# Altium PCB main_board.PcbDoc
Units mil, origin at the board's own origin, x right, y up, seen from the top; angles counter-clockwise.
Board outline 7810 x 5890 mil, 2 copper layers (Top Layer, Bottom Layer); 105 components, 115 nets, 422 pads, 69 vias.
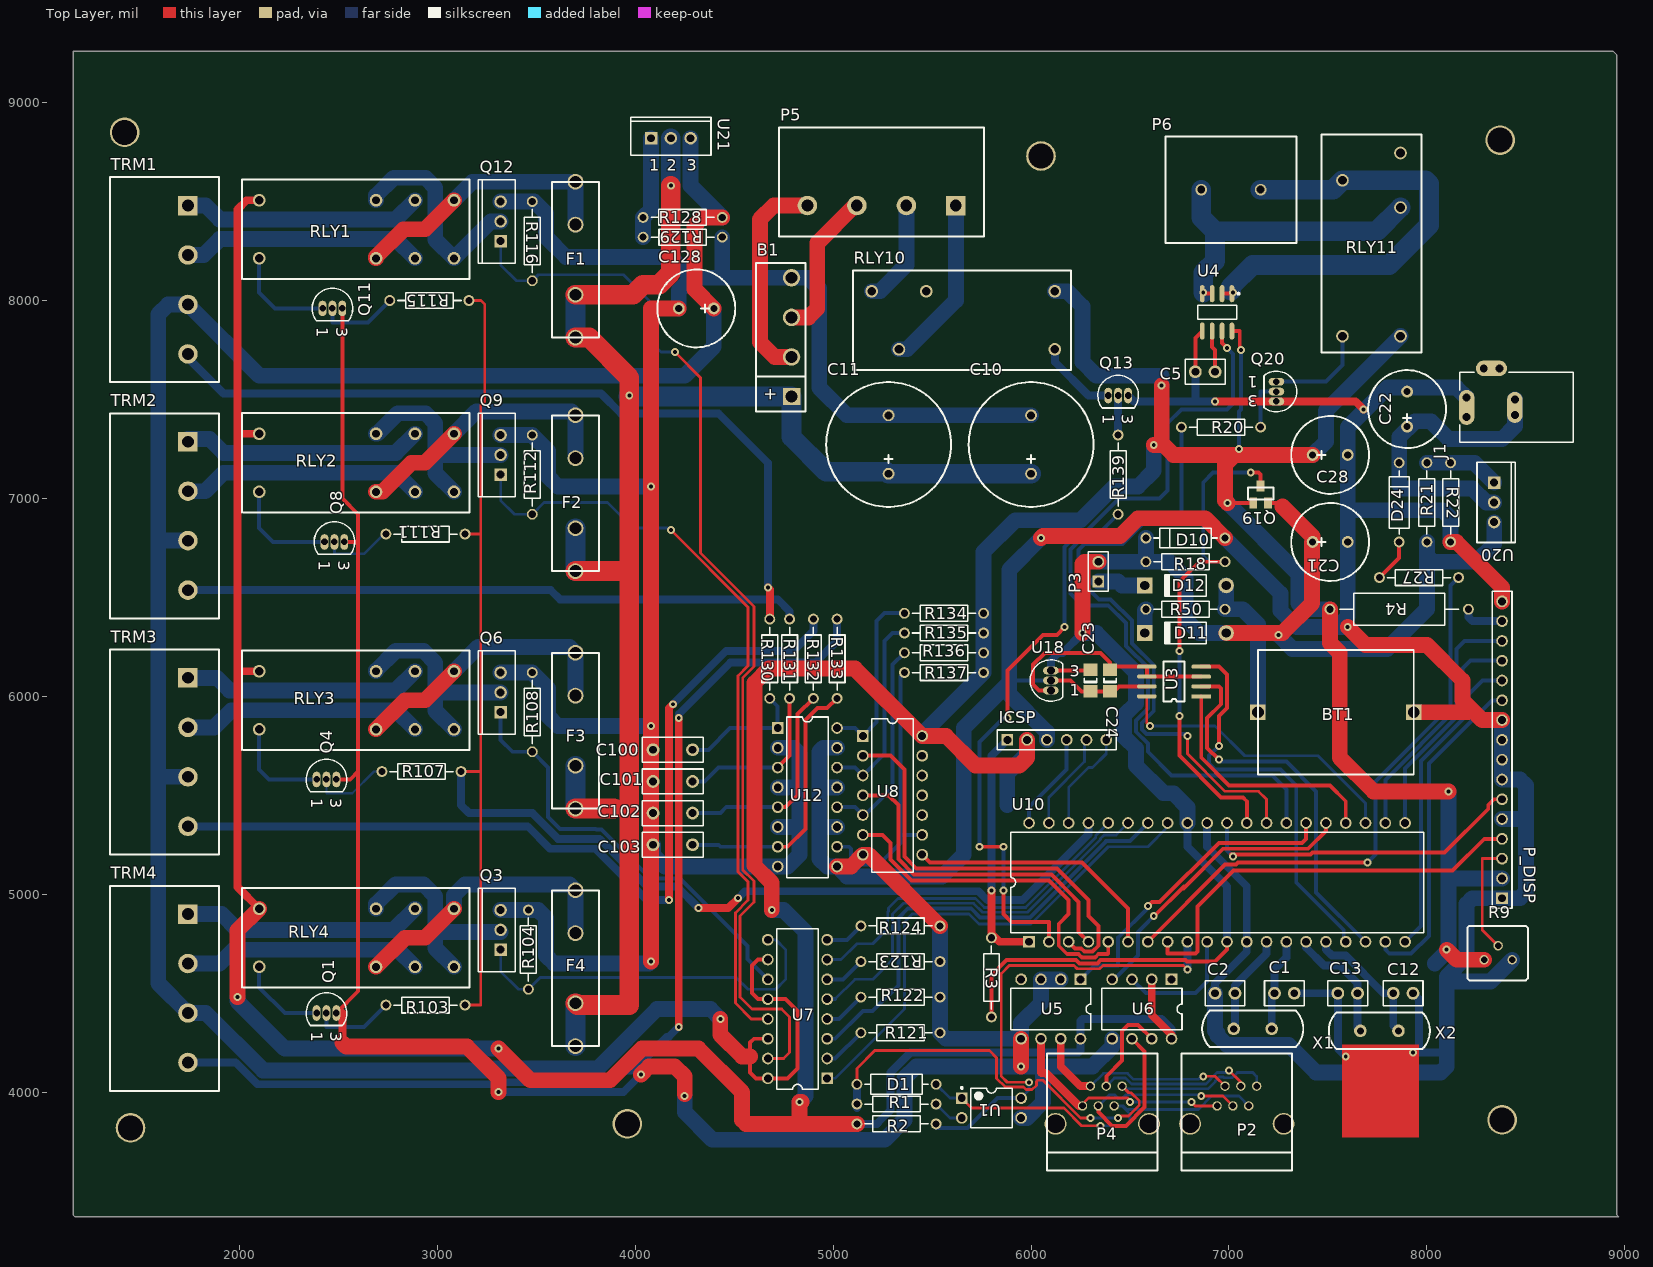
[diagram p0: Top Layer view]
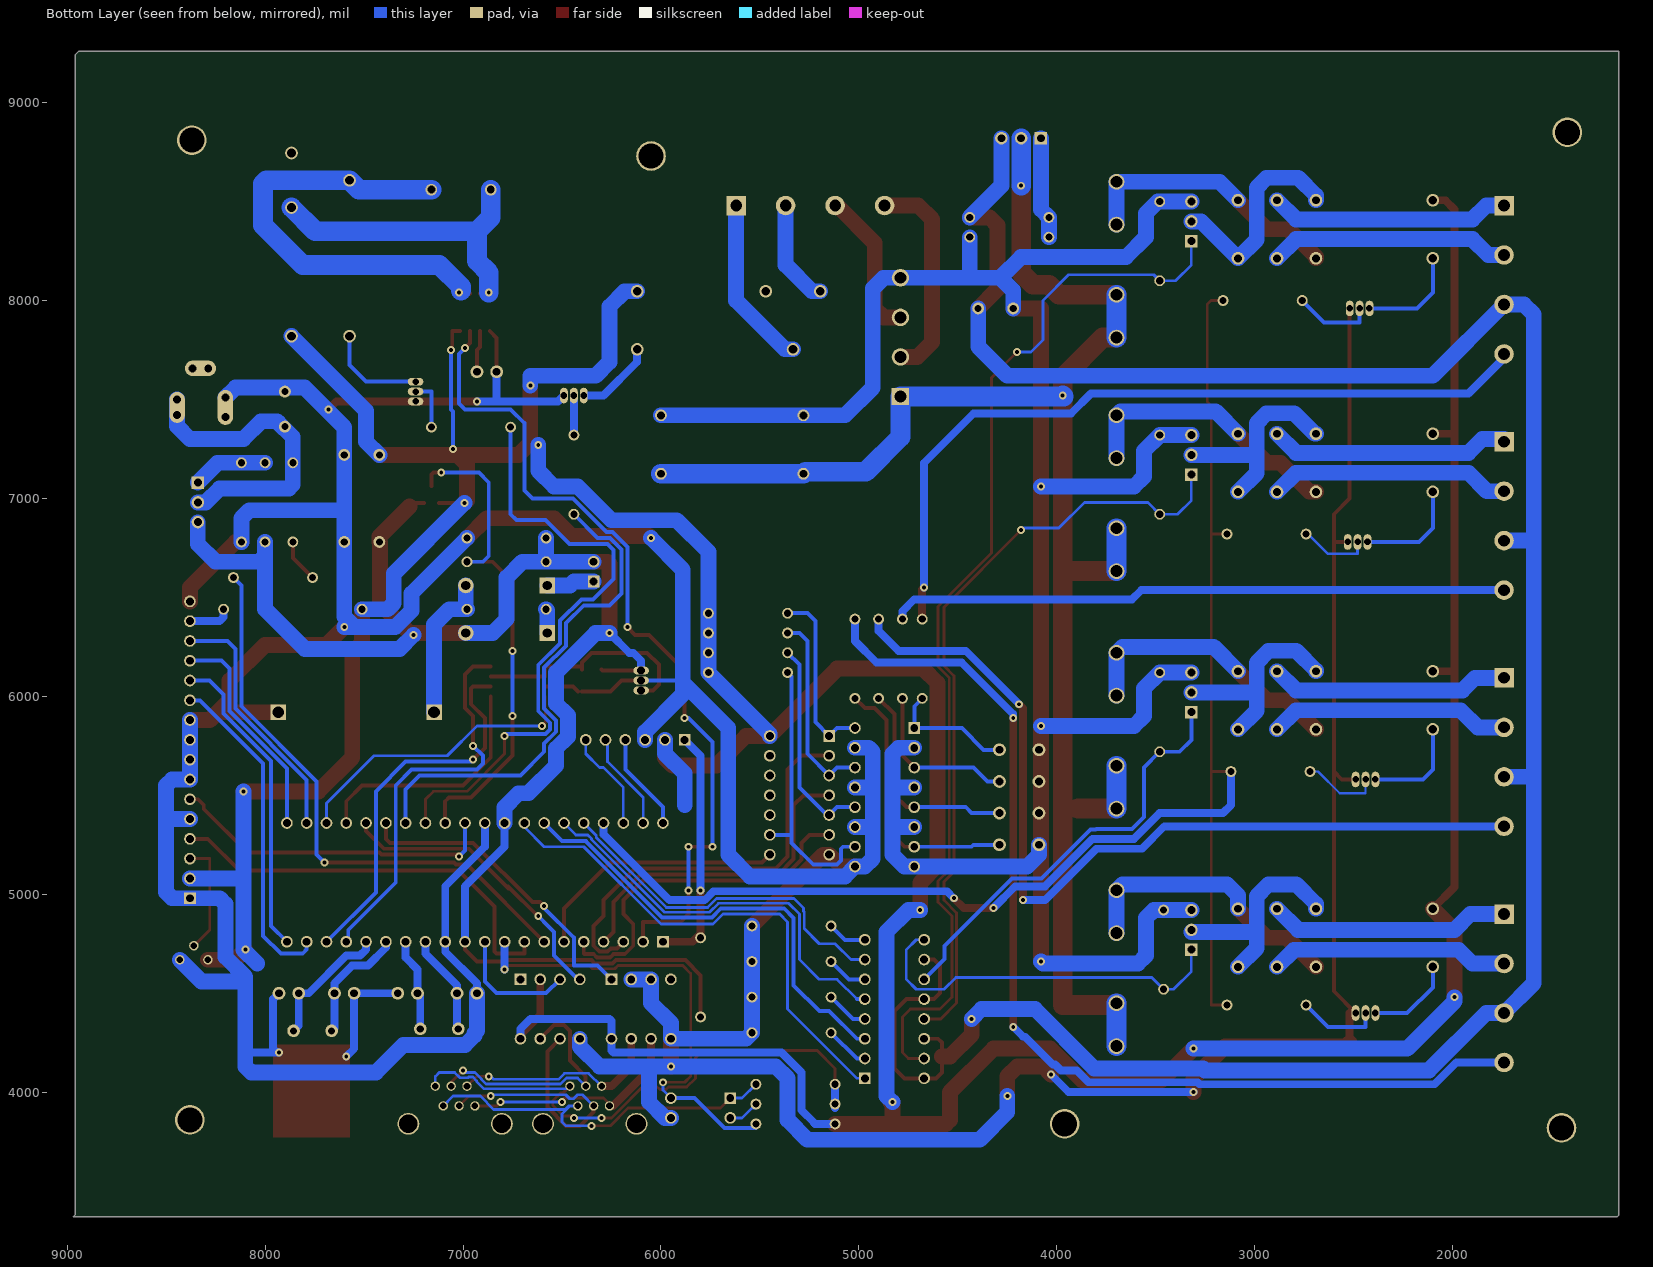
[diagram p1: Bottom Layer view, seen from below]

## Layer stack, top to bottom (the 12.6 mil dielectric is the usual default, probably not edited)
Top Layer: signal copper 1.4
Dielectric: dielectric 12.6, FR-4, Dk 4.8
Bottom Layer: signal copper 1.4

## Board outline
1160,3490 1160,9260 8940,9260 8960,9240 8960,3380 8970,3370 1170,3370 1160,3380

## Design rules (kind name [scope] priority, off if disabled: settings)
Clearance [All] p1: gap=10
ComponentClearance [All] p1: gap=10 collisioncheckmode=3 verticalgap=10
PolygonConnect [All] p1: connectstyle=Relief reliefconductorwidth=10 reliefentries=4 polygonreliefangle="90 Angle"
RoutingCorners [All] p1: cornerstyle=45-Degree minsetback=20 maxsetback=20
RoutingPriority [InNet('GND')] p1: routingpriority=0
RoutingVias [All] p1: holewidth=20 width=40 viastyle="Through Hole" minholewidth=20 minwidth=40 maxholewidth=20 maxwidth=40
SolderMaskExpansion [All] p1: expansion=4
TestPointUsage [All] p1: valid=0 allowmultiple=FALSE
Testpoint [(IsPad And (OnTopLayer Or OnBottomLayer))] p1: side=3 testpointundercomponent=TRUE minsize=40 maxsize=100 preferedsize=60 minholesize=0 maxholesize=40 preferedholesize=32 testpointgrid=1 style=297 order=0-112345678
Width [All] p1: maxlimit=100 minlimit=10 preferedwidth=14
16 further rules are at their usual default settings.

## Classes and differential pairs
component class "Sensor frontend": C100 C101 C102 C103 D1 R1 R2 R130 R131 R132 R133 R134 R135 R136 R137 U1 U8 U12
component class main: BT1 C1 C2 C5 C12 C13 C21 C22 C23 C24 C28 D10 D11 D12 D24 ICSP J1 P2 P3 P4 P6 P_DISP Q19 Q20 R3 R4 R9 R18 R20 R21 R22 R27 R50 RLY9 RLY11 U3 U4 U5 U6 U10 U18 U20 U? X1 X2
component class MTR_DRV1: B1 C10 C11 C128 F1 F2 F3 F4 P5 Q1 Q3 Q4 Q6 Q8 Q9 Q11 Q12 Q13 R103 R104 R107 R108 R111 R112 R115 R116 R121 R122 R123 R124 R128 R129 R139 RLY1 RLY2 RLY3 RLY4 RLY10 TRM1 TRM2 TRM3 TRM4 U7 U21 »»»

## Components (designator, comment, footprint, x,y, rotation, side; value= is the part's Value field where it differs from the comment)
B1 "BRIDGE" BRIDGE 4860,7440 r90 top
BT1 "Battery" batt 7540,5920 r180 top
C1 "Cap" VP32-3.2 7280,4500 r180 top
C2 "Cap" VP32-3.2 6980,4500 r0 top
C5 "Cap" VP32-3.2 6880,7640 r0 top
C10 "Cap Pol1" Capacitor2200u50v 6000,7420 r270 top
C11 "Cap Pol1" Capacitor2200u50v 5280,7420 r270 top
C12 "Cap" VP32-3.2 7880,4500 r180 top
C13 "Cap" VP32-3.2 7600,4500 r0 top
C21 "Cap" Capacitor470u25v 7600,6780 r180 top
C22 "Cap" Capacitor470u25v 7900,7540 r270 top
C23 "Cap Semi" C1206 6300,6080 r90 top
C24 "Cap Semi" C1206 6400,6080 r90 top
C28 "Cap" Capacitor470u25v 7600,7220 r180 top
C100 "Cap" VP45-3.2 4190,5730 r0 top
C101 "Cap" VP45-3.2 4190,5570 r0 top
C102 "Cap" VP45-3.2 4190,5410 r0 top
C103 "Cap" VP45-3.2 4190,5250 r0 top
C128 "Cap" Capacitor470u25v 4220,7960 r0 top
D1 "13V" DIODE-0.4 5320,4040 r0 top
D10 "6V" DIODE-0.4 6780,6800 r180 top
D11 "Diode 1N4001" DO-41 6780,6320 r180 top
D12 "5817" DO-41 6780,6560 r180 top
D24 "9V" DIODE-0.4 7860,6980 r90 top
F1 "Fuse5mm" Fuse5mm 3580,8600 r270 top
F2 "Fuse5mm" Fuse5mm 3580,7420 r270 top
F3 "Fuse5mm" Fuse5mm 3580,6220 r270 top
F4 "Fuse5mm" Fuse5mm 3580,5020 r270 top
ICSP "Header 6" HDR1X6 5880,5780 r0 top
J1 "PWR2.5" KLD-0202 8740,7460 r180 top
P2 "Header 6" PHONE_6 7040,3840 r0 top
P3 "Header 2" HDR1X2 6340,6580 r90 top
P4 "Header 6" PHONE_6 6360,3840 r0 top
P5 "4XTERMINAL" BLK_TERMX4 5620,8480 r180 top
P6 "Header 2" BLOCK_X2_762mm 6860,8560 r0 top
P_DISP "Header 16" HDR1X16 8380,4980 r90 top
Q1 "P2N2222A" 29-04 2440,4400 r270 top
Q3 "IRF3205" TO-220AB 3320,4820 r90 top
Q4 "P2N2222A" 29-04 2440,5580 r270 top
Q6 "IRF3205" TO-220AB 3320,6020 r90 top
Q8 "P2N2222A" 29-04 2480,6780 r270 top
Q9 "IRF3205" TO-220AB 3320,7220 r90 top
Q11 "P2N2222A" 29-04 2470,7960 r270 top
Q12 "IRF3205" TO-220AB 3320,8400 r90 top
Q13 "P2N2222A" 29-04 6440,7520 r270 top
Q19 "IRHM9150" "SSOT-3 - duplicate" 7160,7020 r0 top
Q20 "P2N2222A" 29-04 7240,7540 r180 top
R1 "Res1" AXIAL-0.4 5320,3940 r180 top
R2 "Res1" AXIAL-0.4 5320,3840 r0 top
R3 "Res1" AXIAL-0.4 5800,4580 r270 top
R4 "Res1" AXIAL-0.7 7860,6440 r180 top
R9 "Res Tap" RPOT 8360,4740 r180 top
R18 "Res1" AXIAL-0.4 6780,6680 r0 top
R20 "Res1" AXIAL-0.4 6960,7360 r180 top
R21 "Res1" AXIAL-0.4 8000,6980 r90 top
R22 "Res1" AXIAL-0.4 8120,6980 r270 top
R27 "Res1" AXIAL-0.4 7960,6600 r0 top
R50 "Res1" AXIAL-0.4 6780,6440 r180 top
R103 "Res1" AXIAL-0.4 2940,4440 r0 top
R104 "Res1" AXIAL-0.4 3460,4720 r270 top
R107 "Res1" AXIAL-0.4 2920,5620 r0 top
R108 "Res1" AXIAL-0.4 3480,5920 r270 top
R111 "Res1" AXIAL-0.4 2940,6820 r0 top
R112 "Res1" AXIAL-0.4 3480,7120 r270 top
R115 "Res1" AXIAL-0.4 2960,8000 r0 top
R116 "Res1" AXIAL-0.4 3480,8300 r270 top
R121 "Res1" AXIAL-0.4 5340,4300 r180 top
R122 "Res1" AXIAL-0.4 5340,4480 r180 top
R123 "Res1" AXIAL-0.4 5340,4660 r180 top
R124 "Res1" AXIAL-0.4 5340,4840 r180 top
R128 "Res1" AXIAL-0.4 4240,8420 r180 top
R129 "Res1" AXIAL-0.4 4240,8320 r0 top
R130 "Res1" AXIAL-0.4 4680,6190 r90 top
R131 "Res1" AXIAL-0.4 4780,6190 r90 top
R132 "Res1" AXIAL-0.4 4900,6190 r90 top
R133 "Res1" AXIAL-0.4 5020,6190 r90 top
R134 "Res1" AXIAL-0.4 5560,6420 r180 top
R135 "Res1" AXIAL-0.4 5560,6320 r180 top
R136 "Res1" AXIAL-0.4 5560,6220 r180 top
R137 "Res1" AXIAL-0.4 5560,6120 r180 top
R139 "Res1" AXIAL-0.4 6440,7120 r90 top
RLY1 "RELAY2" DPDT_Relay 2100,8360 r180 top
RLY2 "RELAY2" DPDT_Relay 2100,7180 r180 top
RLY3 "RELAY2" DPDT_Relay 2100,5980 r180 top
RLY4 "RELAY2" DPDT_Relay 2100,4780 r180 top
RLY10 "RELAY1" SPDT 6120,7900 r0 top
RLY11 "RELAY1" SPDT 7720,7820 r270 top
TRM1 "4XTERMINAL" BLK_TERMX4 1740,8480 r270 top
TRM2 "4XTERMINAL" BLK_TERMX4 1740,7286.67 r270 top
TRM3 "4XTERMINAL" BLK_TERMX4 1740,6093.33 r270 top
TRM4 "4XTERMINAL" BLK_TERMX4 1740,4900 r270 top
U1 "Optoisolator1" DIP-4 5800,3920 r0 top
U3 "AT45DB161" SOP8 6860,6000 r180 top
U4 "ACS712" 751-05_N 6940,7940 r270 top
U5 "RS485 (RX)" PA8 6100,4420 r180 top
U6 "RS485 (TX)" PA8 6560,4420 r180 top
U7 "ILD74" DIP-16 4820,4420 r90 top
U8 "MC74HC14AN" 646-06 5300,5500 r270 top
U10 "PIC18F458-E/P" PDIP600-40 6940,5060 r0 top
U12 "ILD74" DIP-16 4870,5490 r270 top
U18 "L78L05ABZ" TO92 6100,6080 r0 top
U20 "LM317T" 221A-06 8340,6980 r270 top
U21 "LM317T" 221A-06 4180,8820 r0 top
X1 "XTAL" XTAL 7120,4320 r0 top
X2 "XTAL" XTAL 7760,4310 r180 top

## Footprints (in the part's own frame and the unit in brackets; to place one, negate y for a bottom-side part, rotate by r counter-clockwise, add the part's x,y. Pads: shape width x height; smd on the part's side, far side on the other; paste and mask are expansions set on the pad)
29-04 [mm] "TO, Flat Index; 3 In-Line, Axial Leads; Body Dia. 4.8mm; Leads 0.48 x 0.5 mm (max)"
  oval 2x1 hole 0.838: 1(0,-1.27) 2(0,0) 3(0,1.27)
  silkscreen extent -2.6,-2.6 1.6,2.6
221A-06 [mm] "TO, Thru-Hole, Vertical, Heatsink Mounted; 3 In-Line Leads; Pitch 2.54 mm"
  rect 1.6x1.6 hole 1.016: 1(-2.54,0)
  round 1.6 hole 1.016: 2(0,0) 3(2.54,0)
  silkscreen extent -5.15,-2.2 5.15,2.7
646-06 [mm] "DIP; 14 Leads; Row Spacing 7.62 mm; Pitch 2.54 mm"
  rect 1.5x1.5 hole 1.016: 1(-7.62,-3.81)
  round 1.5 hole 1.016: 2(-5.08,-3.81) 3(-2.54,-3.81) 4(0,-3.81) 5(2.54,-3.81) 6(5.08,-3.81) 7(7.62,-3.81) 8(7.62,3.81) 9(5.08,3.81) 10(2.54,3.81) 11(0,3.81) 12(-2.54,3.81) 13(-5.08,3.81) 14(-7.62,3.81)
  silkscreen extent -9.85,-2.65 9.85,2.65
751-05_N [mm] "SOIC, 8-Leads, Body 4.9x3.9mm, Pitch 1.27mm, IPC Medium Density"
  oval 2.2x0.6 smd: 1(-2.4,1.905) 2(-2.4,0.635) 3(-2.4,-0.635) 4(-2.4,-1.905) 5(2.4,-1.905) 6(2.4,-0.635) 7(2.4,0.635) 8(2.4,1.905)
  silkscreen extent -2.52,-2.5 0.9,2.88, body extent -2,-2.5 2,2.5, height 1.75
AXIAL-0.4 [mm] "Axial Device, Thru-Hole; 2 Leads; 0.4 in Pin Spacing"
  round 1.4 hole 0.914: 1(-5.08,0) 2(5.08,0)
  silkscreen extent -4.06,-1.02 4.06,1.02
AXIAL-0.7 [mm] "Variable Resistor; 2 Leads"
  round 1.4 hole 0.914: 1(-8.89,0) 2(8.89,0)
  silkscreen extent -7.62,-2.03 7.62,2.03
batt [mm]
  rect 2x2 hole 1.5: 1(10,0) 2(-10,0)
  silkscreen extent -10,-8 10,8
BLK_TERMX4 [mm] "4 PIN BLOCK TERMINCAL (6.35MM PITCH)"
  rect 2.5x2.5 hole 1.5: 0(0,0)
  round 2.5 hole 1.5: 1(6.35,0) 2(12.7,0) 3(19.05,0)
  silkscreen extent -3.63,-10 22.68,4
BLOCK_X2_762mm [mm]
  round 1.5 hole 1.016: 1(0,0) 2(7.62,0)
  silkscreen extent -4.6,-6.85 12.22,6.85
BRIDGE [mil] "KBL401"
  rect 88x88 hole 60: 1(75,70)
  round 88 hole 60: 2(275,70) 3(475,70) 4(675,70)
  silkscreen extent 0,0 750,250
C1206 [mm] "Chip Capacitor; Body 3.2 x 1.6 mm (LxW typ)"
  rect 1.6x1.8 smd: 1(-1.4,0) 2(1.4,0)
  silkscreen extent -0.3,-0.8 0.3,0.8
Capacitor470u25v [mil]
  round 60 hole 36: 1(177.17,0) 2(0,0)
  silkscreen extent -108,-197 285,197
Capacitor2200u50v [mil]
  round 60 hole 40: 1(295.28,0) 2(0,0)
  silkscreen extent -167,-315 462,315
DIODE-0.4 [mm] "Diode, Thru-Hole; 2 Leads; 0.4 in Pin Spacing"
  round 1.4 hole 0.914: 1(-5.08,0) 2(5.08,0)
  silkscreen extent -4.06,-1.27 4.06,1.27
DIP-4 [mm] "DIP; 4 Leads; Row Spacing 7.62 mm; Pitch 2.54 mm"
  rect 1.5x1.5 hole 1.016: 1(-3.81,1.27)
  round 1.5 hole 1.016: 2(-3.81,-1.27) 3(3.81,-1.27) 4(3.81,1.27)
  silkscreen extent -3.93,-2.55 2.65,2.69, body extent -3.15,-2.5 3.15,2.5, height 5.6
DIP-16 [mm] "DIP; 16 Leads; Row Spacing 7.62 mm; Pitch 2.54 mm"
  rect 1.5x1.5 hole 1.016: 1(-8.89,-3.81)
  round 1.5 hole 1.016: 2(-6.35,-3.81) 3(-3.81,-3.81) 4(-1.27,-3.81) 5(1.27,-3.81) 6(3.81,-3.81) 7(6.35,-3.81) 8(8.89,-3.81) 9(8.89,3.81) 10(6.35,3.81) 11(3.81,3.81) 12(1.27,3.81) 13(-1.27,3.81) 14(-3.81,3.81) 15(-6.35,3.81) 16(-8.89,3.81)
  silkscreen extent -10.3,-2.65 10.3,2.65
DO-41 [mm] "Diode, Axial; Body 5.2 x 2.7 mm (LxDia. max), Lead Dia. 0.86 mm (max)"
  round 2 hole 1.2: 1(-5.23,0)
  rect 2x2 hole 1.2: 2(5.23,0)
  silkscreen extent -2.65,-1.4 2.74,1.4
DPDT_Relay [mm]
  round 1.626 hole 1.016: 1(-25,3.725) 2(-20,3.725) 3(-15,3.725) 6(-15,-3.725) 7(-20,-3.725) 8(-25,-3.725)
  round 1.626 hole 1.118: 4(0,3.725) 5(0,-3.725)
  silkscreen extent -27,-6.4 2.2,6.4
Fuse5mm [mil]
  round 80 hole 60: 1(0,118.11) 2(216.54,118.11) 3(570.87,118.11) 4(787.4,118.11)
  silkscreen extent 0,0 787,236
HDR1X2 [mm] "Connector; Header; 2 Position"
  rect 1.5x1.5 hole 1.016: 1(0,0)
  round 1.5 hole 1.016: 2(2.54,0)
  silkscreen extent -1.27,-1.27 3.81,1.27
HDR1X6 [mm] "Connector; Header; 6 Position"
  rect 1.5x1.5 hole 1.016: 1(0,0)
  round 1.5 hole 1.016: 2(2.54,0) 3(5.08,0) 4(7.62,0) 5(10.16,0) 6(12.7,0)
  silkscreen extent -1.27,-1.27 13.97,1.27
HDR1X16 [mm] "Connector; Header; 16 Position"
  rect 1.5x1.5 hole 1.016: 1(0,0)
  round 1.5 hole 1.016: 2(2.54,0) 3(5.08,0) 4(7.62,0) 5(10.16,0) 6(12.7,0) 7(15.24,0) 8(17.78,0) 9(20.32,0) 10(22.86,0) 11(25.4,0) 12(27.94,0) 13(30.48,0) 14(33.02,0) 15(35.56,0) 16(38.1,0)
  silkscreen extent -1.27,-1.27 39.37,1.27
KLD-0202 [mm] "DC Power Jack, 2.5mm, KLD Series, PCB Mount"
  oval 2x4.5 all layers, no hole: 1(13.7,0)
  round 1.5 hole 1.016: 1A(13.7,-1.25) 1B(13.7,1.25) 2A(7.5,-1) 2B(7.5,1) 3A(9.5,-5) 3B(11.5,-5)
  oval 2x4 all layers, no hole: 2(7.5,0)
  oval 4x2 all layers, no hole: 3(10.5,-5)
  silkscreen extent 0,-4.5 14.6,4.5
PA8 [mm] "DIP; 8 Leads; Row Spacing 7.62 mm; Pitch 2.54 mm"
  rect 1.5x1.5 hole 1.016: 1(-3.81,-3.81)
  round 1.5 hole 1.016: 2(-1.27,-3.81) 3(1.27,-3.81) 4(3.81,-3.81) 5(3.81,3.81) 6(1.27,3.81) 7(-1.27,3.81) 8(-3.81,3.81)
  silkscreen extent -5.15,-2.65 5.15,2.65
PDIP600-40 [mm] "DIP, Plastic; 40 Leads; Row Spacing 15.24 mm; Pitch 2.54 mm"
  rect 1.5x1.5 hole 1.016: 1(-24.13,-7.62)
  round 1.5 hole 1.016: 2(-21.59,-7.62) 3(-19.05,-7.62) 4(-16.51,-7.62) 5(-13.97,-7.62) 6(-11.43,-7.62) 7(-8.89,-7.62) 8(-6.35,-7.62) 9(-3.81,-7.62) 10(-1.27,-7.62) 11(1.27,-7.62) 12(3.81,-7.62) 13(6.35,-7.62) 14(8.89,-7.62) 15(11.43,-7.62) 16(13.97,-7.62) 17(16.51,-7.62) 18(19.05,-7.62) 19(21.59,-7.62) 20(24.13,-7.62) 21(24.13,7.62) 22(21.59,7.62) 23(19.05,7.62) 24(16.51,7.62) 25(13.97,7.62) 26(11.43,7.62) 27(8.89,7.62) 28(6.35,7.62) 29(3.81,7.62) 30(1.27,7.62) 31(-1.27,7.62) 32(-3.81,7.62) 33(-6.35,7.62) 34(-8.89,7.62) 35(-11.43,7.62) 36(-13.97,7.62) 37(-16.51,7.62) 38(-19.05,7.62) 39(-21.59,7.62) 40(-24.13,7.62)
  silkscreen extent -26.5,-6.45 26.5,6.45
PHONE_6 [mm] "6 pin modular phone jack"
  round 2.8 hole 2.4: 0(-6,0) 0(6,0)
  round 1.2 hole 0.838: 1(-2.54,2.3) 2(-1.525,4.84) 3(-0.51,2.3) 4(0.51,4.84) 5(1.525,2.3) 6(2.54,4.84)
  silkscreen extent -7.1,-6 7.1,9
RPOT [mil]
  round 48 hole 33: 1(-71,71) 2(0,0) 3(71,71)
  silkscreen extent -150,-100 155,175
SOP8 [mil]
  rect 100x20 smd: 1(0,0)
  oval 100x20 smd: 2(0,-50) 3(0,-100) 4(0,-150) 5(275,-150) 6(275,-100) 7(275,-50) 8(275,0)
  silkscreen extent 85,-175 190,25
SPDT [mm] "1 From C relay"
  round 1.626 hole 1.118: 1(-20,-3.725) 2(0,3.725) 3(-23.5,3.725) 4(-16.5,3.725) 5(0,-3.725)
  silkscreen extent -25.9,-6.4 2.1,6.4
"SSOT-3 - duplicate" [mm]
  rect 1x1.4 smd: 1(-0.95,-1.1) 2(0.95,-1.1) 3(0,1.1)
  silkscreen extent -1.65,-0.64 1.65,0.89
TO92 [mm] "TO, Flat Index; 3 In-Line, Axial Leads; Body Dia. 4.8mm; Leads 0.51 x 0.51 mm (max)"
  oval 2x1 hole 1.016: 1(0,-1.27) 2(0,0) 3(0,1.27)
  silkscreen extent -2.65,-2.65 1.55,2.65
TO-220AB [mm] "TO, Thru-Hole, Vertical, Heatsink Mounted; 3 In-Line Leads; Pitch 2.54 mm"
  rect 1.6x1.6 hole 1.016: 1(-2.54,0)
  round 1.6 hole 1.016: 2(0,0) 3(2.54,0)
  silkscreen extent -5.35,-1.85 5.35,2.85
VP32-3.2 [mm] "Capacitor, Ceramic, Thru-Hole, Dipped Radial; Body 5.1 x 3.2 mm (WxT) Pin Spacing 2.54 mm (typ)"
  round 1.65 hole 1.016: 1(-1.27,0) 2(1.27,0)
  silkscreen extent -2.55,-1.6 2.55,1.6
VP45-3.2 [mm] "Capacitor, Ceramic, Thru-Hole, Dipped Radial; Body 7.8 x 3.2 mm (WxT) Pin Spacing 5.08 mm (typ)"
  round 1.65 hole 1.016: 1(-2.54,0) 2(2.54,0)
  silkscreen extent -3.9,-1.6 3.9,1.6
XTAL [mil]
  round 64.02 hole 36: 0(-96.06,0) 1(96.06,0)
  silkscreen extent -255,-92 255,92

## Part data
BT1: "Multicell Battery"
C1 C2 C5 C12 C13 C21 C22 C28 C100 C101 C102 C103 C128: "Capacitor"
C10 C11: "Polarized Capacitor (Radial)"
C23 C24: "Capacitor (Semiconductor SIM Model)"
D1 D10 D24: library part "D Zener", "Zener Diode"
D11: "1 Amp General Purpose Rectifier"
D12: library part "Diode 1N4001", "1 Amp General Purpose Rectifier"
ICSP P2 P4: "Header, 6-Pin"
J1: "Low Voltage Power Supply Connector"
P3 P6: "Header, 2-Pin"
P_DISP: "Header, 16-Pin"
Q1 Q4 Q8 Q11 Q13 Q20: "Amplifier Transistor NPN Silicon"
Q3 Q6 Q9 Q12: "HEXFET Power MOSFET"
Q19: "Radiation Hardened HEXFET Power MOSFET"
R1 R2 R3 R4 R18 R20 R21 R22 R27 R50 R103 R104 R107 R108 R111 R112 R115 R116 R121 R122 R123 R124 R128 R129 R130 R131 R132 R133 R134 R135 R136 R137 R139: "Resistor"
R9: "Tapped Resistor"
U1: "4-Pin Phototransistor Optocoupler"
U5 U6: library part MAX485EPA, "Low-Power, Slew-Rate-Limited RS-485/RS-422 Transceiver"
U7 U12: "Optocoupler, Phototransistor Output, Dual Channel, TTL Compatible, Pb-free"
U8: "Hex Schmitt Trigger Inverter"
U10: "High Performance, Enhanced FLASH Microcontroller with CAN, 32K FLASH, 40-Pin PDIP, Standard Volt Range, Extended Temperature"
U18: "Positive Voltage Regulator"
U20 U21: "Three-Terminal Adjustable Output Positive Voltage Regulator"

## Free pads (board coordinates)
  round 149.61 hole 125.98: 0(8380,3860) 1(8370,8810) 3(3960,3840) 3(6050,8730) 4(1450,3820) 5(1420,8850)

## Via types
v1: diameter 40, hole 20, Top Layer to Bottom Layer, 69 vias

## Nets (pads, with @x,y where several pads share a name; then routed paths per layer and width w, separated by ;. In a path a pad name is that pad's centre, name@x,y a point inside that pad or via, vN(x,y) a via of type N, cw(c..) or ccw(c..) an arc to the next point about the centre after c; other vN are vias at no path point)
GND: BT1.2 C1.1 C2.1 C5.1 C12.1 C13.1 C21.2 C22.2 C23.1 C24.1 C28.2 D10.1 ICSP.3 J1.1 J1.1A J1.1B P_DISP.1 P_DISP.5 P_DISP.7 P_DISP.8 P_DISP.9 P_DISP.10 P_DISP.16 Q1.3 Q4.3 Q8.3 Q11.3 Q13.3 Q20.3 R9.1 R22.2 R121.1 R122.1 R123.1 R124.1 U1.3 U3.7 U4.5 U5.2 U5.3 U5.5 U6.5 U8.7 U10.12 U10.31 U12.9 U12.11 U12.13 U12.15 U18.2 | length 29467.7
  Top Layer w20: Q1.3 2600,4510 2600,6920 2520,7000 Q11.3 ; Q4.3 2560,5580 2600,5620 ; Q8.3 2600,6780 ; U18.2 6200,6080 6255.12,6024.88 C23.1 C24.1 ; C24.1@6420,6024.88 6445.12,6050 U3.7 ; C5.1 6830,7810.51 U4.5
  Top Layer w40: 2510,4400 2520,4400 2520,4250 ; v1(6930,7490) Q20.3 7640,7490 v1(7680,7450)
  Top Layer w80: 2520,4250 2540,4230 3150,4230 3310,4070 v1(3310,4000) ; v1(4030,4090) 4070,4130 4200,4130 4250,4080 v1@4250,3990 ; U12.9 5090,5140 U8.7 5180,5200 R124.1 ; v1(5950,4130) U5.5 ; v1(6050,6800) 6060,6810 6450,6810 6540,6900 6880,6900 D10.1 ; v1(7600,6350) 7690,6260 8000,6260 8180,6080 8180,5980 8223.64,5936.36 ; BT1.2 8207.27,5920 8223.64,5936.36 ; R22.2 8150,6780 8380,6550 P_DISP.16 ; P_DISP.10 8280,5880 8223.64,5936.36
  Bottom Layer w20: 5890,6070 5900,6080 U18.2
  Bottom Layer w40: v1(3310,4000) 3940,4000 v1(4030,4090) ; Q13.3 6520,7490 6830,7490 ; C5.1 6830,7490 ; U10.31 6890,5240 7090,5040 U10.12 7090,4710 6930,4550 C2.1 ; v1(6930,7490) 6830,7490 ; C1.1 C13.1 7550,4220 v1(7590,4180) ; v1(7930,4200) v1@7940,4200 ; C12.1 7960,4470 7960,4220 v1@7940,4200 ; 8100,4210 8090,4200 v1@7940,4200
  Bottom Layer w80: v1(4250,3980) 4250,3900 4390,3760 5260,3760 5360,3860 5360,4070 5420,4130 v1(5950,4130) 6060,4130 ; 4960,5340 U12.11 ; 4960,5540 U12.13 ; U12.15 4950,5740 4930,5720 4930,5180 4970,5140 U12.9 5070,5090 5550,5090 5660,5200 5660,5840 5890,6070 ; R124.1 R123.1 R122.1 R121.1 5570,4270 U5.5 5950,4350 6050,4450 U5.3 U5.2 ; U1.3 5980,3870 6060,3950 6060,4130 ; v1(6050,6800) 5890,6640 5890,6070 ; ICSP.3 6080,5820 5890,6010 5890,6070 ; U6.5 6410,4230 6310,4130 6060,4130 ; C2.1 6930,4310 6941.93,4298.07 6941.93,4286.03 6989.97,4237.99 7302.01,4237.99 7440,4100 8070,4100 8100,4130 8100,4210 8100,4582.72 ; D10.1 7260,6520 7260,6432.72 7342.72,6350 7547.28,6350 ; v1(7600,6350) 7547.28,6350 ; R22.2 8120,6900 8080,6940 7600,6940 ; J1.1A 8149.84,7560 7800,7560 7600,7360 C28.2 7600,6940 ; P_DISP.5 8490,5380 8500,5390 ; P_DISP.10 P_DISP.9 P_DISP.8 P_DISP.7 8470,5580 8500,5550 8500,5390 ; R9.1 8322,4560 8122.72,4560 8100,4582.72 ; 7547.28,6350 7600,6402.72 C21.2 7600,6940 ; 8100,4582.72 8200,4682.72 8200,4950 8230,4980 P_DISP.1 8470,4980 8500,5010 8500,5390
HVGND: B1.4 C10.2 C11.2 C100.1 C101.1 C102.1 C103.1 C128.2 Q3.3 Q6.3 Q9.3 Q12.3 R104.1 R108.1 R112.1 R116.1 R129.2 U12.2 U12.4 U12.6 U12.8 | length 11844.6
  Top Layer w80: v1(4080,4660) 4080,7960 C128.2
  Bottom Layer w80: Q3.3 3510,4920 3550,4880 3550,4690 3590,4650 4050,4650 ; Q6.3 R108.1 3560,6040 3560,5900 3610,5850 v1(4080,5850) ; Q9.3 R112.1 3560,7240 3560,7110 3610,7060 v1(4080,7060) ; Q12.3 3490,8500 3550,8440 3550,8320 3650,8220 4180,8220 4285,8115 ; v1@4070,4650 v1(4080,4660) ; C103.1 4090,5200 4150,5140 4770,5140 4830,5200 4830,5710 4800,5740 U12.2 ; C128.2 4220,8050 4285,8115 ; 4440,8125 R129.2 ; U12.6 4820,5340 ; U12.4 4820,5540 ; C10.2 5070,7420 4930,7560 4930,8060 4875,8115 4285,8115
NetB1_2: B1.2 P5.3 | length 1080.1
  Top Layer w80: B1.2 4705,7715 4630,7790 4630,8410 4700,8480 P5.3
NetB1_3: B1.3 P5.2 | length 757.3
  Top Layer w80: B1.3 4875,7915 4920,7960 4920,8290 5110,8480 P5.2
NetBT1_1: BT1.1 D12.1 R50.1 | length 764.1
  Bottom Layer w80: D12.1 6985.91,6445.91 R50.1 7070,6440 7146.3,6363.7 BT1.1
NetC1_2: C1.2 U10.14 X1.1 | length 470.6
  Bottom Layer w40: X1.1 7216.06,4486.06 C1.2 7230,4620 7290,4680 U10.14
NetC2_2: C2.2 U10.13 X1.0 | length 508.8
  Bottom Layer w40: X1.0 7030,4326.06 7030,4540 7190,4700 U10.13
NetC5_2: C5.2 U4.6 | length 211.7
  Top Layer w20: U4.6 6915,7765 6930,7750 C5.2
NetC12_2: C12.2 U10.16 X2.0 | length 671.9
  Bottom Layer w40: U10.16 7490,4720 7520,4690 7590,4690 7780,4500 C12.2 7830,4336.06 X2.0
NetC13_2: C13.2 U10.15 X2.1 | length 610.3
  Bottom Layer w40: U10.15 7390,4730 7480,4640 7560,4640 7650,4550 7650,4323.94 X2.1
NetC100_2: C100.2 R130.1 U12.1 | length 642.1
  Bottom Layer w20: C100.2 4370,5730 4480,5840 U12.1 4720,5950 R130.1
NetC101_2: C101.2 R131.1 U12.3 | length 833.8
  Top Layer w20: U12.3 4780,5700 R131.1
  Bottom Layer w20: C101.2 4350,5570 4420,5640 U12.3
NetC102_2: C102.2 R132.1 U12.5 | length 1090.4
  Top Layer w20: U12.5 4760,5440 4820,5500 4820,5910 R132.1
  Bottom Layer w20: C102.2 4430,5410 4460,5440 U12.5
NetC103_2: C103.2 R133.1 U12.7 | length 1367
  Top Layer w20: U12.7 4770,5240 4860,5330 4860,5880 4920,5940 4970,5940 R133.1
  Bottom Layer w20: C103.2 4420,5250 4430,5240 U12.7
NetD1_1: D1.1 P2.6 P4.6 R1.2 | length 2868.4
  Top Layer w14: D1.1 5120,4120 5210,4210 5790,4210 5826,4174 5826,4070.06 5870.06,4026 5961.67,4026 5974.67,4013 6005.33,4013 6027,4034.67 6027,4053.06 6033.94,4060 6060,4060 6250,3870 v1(6300,3870) ; v1(6440,3870) 6440,3880 6491.8,3880 6547,3935.2 6547,3955.33 6505.33,3997 6493.55,3997 P4.6
  Bottom Layer w14: v1(6300,3870) v1(6440,3870) ; P4.6 6473.55,4017 6893.27,4017 6931,4054.73 6931,4057.06 6949.94,4076 6971.67,4076 6974.67,4073 7015.33,4073 7042.33,4100 7120,4100 7140,4080 P2.6
  Bottom Layer w40: R1.2@5120,3920 D1.1
NetD1_2: D1.2 P2.5 P4.5 U1.1 | length 1908.1
  Top Layer w14: U1.1 5700,3920 6166.06,3920 6256.06,3830 v1(6350,3830)
  Bottom Layer w14: D1.2 5590,3970 U1.1 ; v1(6350,3830) 6480,3830 6500,3850 6500,3890 6459.45,3930.55 ; P4.5 6459.45,3930.55 ; P2.5 7050.59,3980 6912.33,3980 6845.33,3913 6484.67,3913 6467.12,3930.55 6459.45,3930.55
NetD11_2: D11.2 R50.2 | length 122.4
  Bottom Layer w80: D11.2 6574.09,6434.09 R50.2
NetD12_2: D12.2 P3.1 | length 242.4
  Bottom Layer w80: P3.1 6440,6580 6460,6560 D12.2
NetD24_1: D24.1 R27.1 | length 221.4
  Top Layer w20: R27.1 7860,6700 D24.1
NetF1_1: F1.1 F1.2 RLY1.3 RLY1.8 | length 1388.5
  Top Layer w80: RLY1.3 2690.55,8220.55 2830,8360 2937.6,8360 RLY1.8
  Bottom Layer w80: RLY1.8 3177.6,8600 F1.1 F1.2
NetF2_1: F2.1 F2.2 RLY2.3 RLY2.8 | length 1400.8
  Top Layer w80: RLY2.3 2723.35,7033.35 2870,7180 2937.6,7180 RLY2.8
  Bottom Layer w80: RLY2.8 3197.6,7440 3678.11,7440 F2.1 F2.2
NetF3_1: F3.1 F3.2 RLY3.3 RLY3.8 | length 1409.1
  Top Layer w80: RLY3.3 2837.21,5980 2937.6,5980 RLY3.8
  Bottom Layer w80: RLY3.8 3207.6,6250 3668.11,6250 F3.1 F3.2
NetF4_1: F4.1 F4.2 RLY4.3 RLY4.8 | length 1448.7
  Top Layer w80: RLY4.3 2837.21,4780 2937.6,4780 RLY4.8
  Bottom Layer w80: RLY4.8 3084.25,4994.25 3140,5050 3668.11,5050 F4.1 F4.2
NetICSP_1: ICSP.1 R3.1 U10.1 | length 1224.9
  Top Layer w40: v1(5800,5020) 5800,4800 R3.1@5823.68,4776.32 ; R3.1@5820,4772.65 R3.1@5823.68,4776.32 ; U10.1 5840,4760 R3.1@5823.68,4776.32
  Bottom Layer w40: v1(5800,5020) 5800,5700 ICSP.1
NetICSP_4: ICSP.4 U10.40 | length 498.7
  Bottom Layer w20: U10.40 5990,5440 6180,5630 ICSP.4
NetICSP_5: ICSP.5 U10.39 | length 498.7
  Bottom Layer w14: U10.39 6090,5490 6270,5670 6270,5770 ICSP.5
NetICSP_6: ICSP.6 U10.38 | length 510.4
  Bottom Layer w14: U10.38 6190,5540 6290,5640 6310,5640 6380,5710 ICSP.6
NetJ1_3: J1.3 J1.3A J1.3B
NetP2_1: P2.1 P4.1 U5.6 | length 1189.4
  Top Layer w14: P4.1 6260,3940 6291.17,3971.17 6436.87,3971.17 6438.04,3970 6490,3970 6510,3950 v1(6500,3950) ; v1(6810,3950) 6829.45,3930.55 P2.1
  Top Layer w40: U5.6 6050,4100 6053,4097 6075.33,4097 6241.77,3930.55 P4.1
  Bottom Layer w14: v1(6500,3950) v1(6810,3950)
NetP2_2: P2.2 P4.2 U5.7 | length 1077.1
  Top Layer w14: v1(6870,4080) 6930.51,4080 P2.2
  Top Layer w40: U5.7 6150,4130 6249.45,4030.55 P4.2
  Bottom Layer w14: P4.2 6300.55,4030.55 6365.17,4095.17 6486.77,4095.17 6516.94,4065 6845,4065 6860,4080 v1(6870,4080)
NetP2_3: P2.3 P4.3 U6.6 | length 1448.4
  Top Layer w14: v1(6860,3980) 6970.47,3980 P2.3
  Top Layer w20: P4.3 6339.92,3900.08 6410,3830 6479.99,3830 6574,3924.01 6574,4206 U6.6
  Bottom Layer w14: P4.3 6396.37,3987 6421.04,3987 6441.05,3966.99 6460.93,3966.99 6480.94,3987 6853,3987 v1(6860,3980)
NetP2_4: P2.4 P4.4 U6.7 | length 1293.4
  Top Layer w14: v1(7000,4110) 7060.08,4049.92 P2.4
  Top Layer w20: P4.4 6380.08,4080.08 6460,4160 6460,4310 6490,4340 6540,4340 U6.7
  Bottom Layer w14: P4.4 6420.7,4071.17 6476.83,4071.17 6507,4041 6883.33,4041 6907,4064.67 6907,4067 6940,4100 7000,4100 v1(7000,4110)
NetP5_0: P5.0 RLY10.1 | length 869.6
  Bottom Layer w80: RLY10.1 5373.35,7753.35 5620,8000 P5.0
NetP5_1: P5.1 RLY10.3 | length 530.4
  Bottom Layer w80: RLY10.3 5236.65,8046.65 5370,8180 P5.1
NetP6_1: P6.1 RLY11.4 U4.3 U4.4 | length 1610
  Top Layer w20: U4.4 U4.3
  Bottom Layer w100: P6.1 6860,8420 6930,8350 ; v1(6870,8040) 6870,8140 6930,8200 6930,8350 ; RLY11.4 7747.05,8350 6930,8350
NetP6_2: P6.2 RLY11.1 U4.1 U4.2 | length 2302.8
  Top Layer w20: U4.2 U4.1 v1(7020,8039.49)
  Bottom Layer w20: v1(7020,8039.49) v1@7020,8050
  Bottom Layer w100: v1@7010,8050 7010,8070 7120,8180 7810,8180 8010,8380 8010,8590 7992.6,8607.4 RLY11.1 7525.94,8560 P6.2
NetP_DISP_3: P_DISP.3 R9.2 | length 573.1
  Top Layer w14: R9.2 8280,4820 8280,5180 P_DISP.3
NetP_DISP_4: P_DISP.4 U10.8 | length 2123.6
  Top Layer w20: U10.8 6690,4700 6830,4700 6840,4710 6840,4937.57 7022.43,5120 8130,5120 8290,5280 P_DISP.4
NetP_DISP_6: P_DISP.6 U10.30 | length 1680.1
  Top Layer w20: v1@7010,5200 7412.43,5200 7422.43,5210 8090,5210 8310,5430 8310,5450 8340,5480 P_DISP.6
  Bottom Layer w20: U10.30 6990,5220 v1(7020,5190)
NetP_DISP_11: P_DISP.11 U10.19 | length 1678.1
  Bottom Layer w20: U10.19 7790,4720 7810,4700 7920,4700 8010,4790 8010,5660 8330,5980 P_DISP.11
NetP_DISP_12: P_DISP.12 U10.20 | length 1581.5
  Bottom Layer w20: U10.20 7970,4840 7970,5672.72 8210,5912.72 8210,6010 8280,6080 P_DISP.12
NetP_DISP_13: P_DISP.13 U10.21 | length 1116.7
  Bottom Layer w20: U10.21 7890,5635.15 8180,5925.15 8180,6140 8220,6180 P_DISP.13
NetP_DISP_14: P_DISP.14 U10.22 | length 1275.7
  Bottom Layer w20: U10.22 7790,5577.57 8150,5937.57 8150,6240 8190,6280 P_DISP.14
NetP_DISP_15: P_DISP.15 R4.1 | length 218.3
  Bottom Layer w40: R4.1 8210,6400 8230,6380 P_DISP.15
NetQ1_1: Q1.1 RLY4.4 | length 447.2
  Bottom Layer w20: RLY4.4 2100,4530 2230,4400 Q1.1
NetQ1_2: Q1.2 R103.1 | length 415.6
  Bottom Layer w20: Q1.2 2440,4330 2630,4330 R103.1
NetQ3_1: Q3.1 R104.2 U7.9 | length 1918.4
  Bottom Layer w14: Q3.1 3320,4610 3410,4520 R104.2 3520,4580 4510,4580 4570,4520 4710,4520 4760,4570 4760,4720 4710,4770 U7.9
NetQ3_2: Q3.2 RLY4.1 RLY4.6 | length 1105.1
  Bottom Layer w80: RLY4.6 2690.55,4950.55 2790,5050 2930,5050 2990,4990 2990,4727.6 RLY4.1 ; 3000,4810 Q3.2@3320,4810
NetQ4_1: Q4.1 RLY3.4 | length 534.1
  Bottom Layer w20: RLY3.4 2100,5630 2150,5580 2270,5580 ; 2250,5580 2270,5580 ; Q4.1 2270,5580
NetQ4_2: Q4.2 R107.1 | length 395.6
  Bottom Layer w12: Q4.2 2440,5510 2570,5510 2680,5620 R107.1
NetQ6_1: Q6.1 R108.2 U7.11 | length 2176.6
  Bottom Layer w20: Q6.1 3320,5780 3380,5720 R108.2 3560,5640 3560,5390 3620,5330 3800,5330 3803,5327 3829.57,5327 4076.57,5080 4226.57,5080 4567,4739.57 4567,4673 U7.11
NetQ6_2: Q6.2 RLY3.1 RLY3.6 | length 1075.1
  Bottom Layer w80: RLY3.6 2690.55,6130.55 2790,6230 2930,6230 2990,6170 2990,5927.6 RLY3.1 ; 2990,6020 Q6.2
NetQ8_1: Q8.1 RLY2.4 | length 542.3
  Bottom Layer w20: RLY2.4 2100,6850 2170,6780 Q8.1
NetQ8_2: Q8.2 R111.1 | length 361.4
  Bottom Layer w14: Q8.2 2480,6720 2630,6720 2730,6820 R111.1
NetQ9_1: Q9.1 R112.2 U7.13 | length 3919.2
  Top Layer w14: v1(4180,6840) 4570,6450 4570,6154.55 4519,6103.55 4519,5113.98 4570,5062.98 4570,4970 4506,4906 4506,4450.06 4586.06,4370 U7.13
  Bottom Layer w14: Q9.1 3320,6990 3390,6920 R112.2 3540,6980 3860,6980 3990,6850 4170,6850 v1(4180,6840)
NetQ9_2: Q9.2 RLY2.1 RLY2.6 | length 1068.7
  Bottom Layer w80: RLY2.6 2696.65,7326.65 2800,7430 2940,7430 2990,7380 2990,7127.6 RLY2.1 ; 3000,7220 Q9.2
NetQ11_1: Q11.1 RLY1.4 | length 546.5
  Bottom Layer w20: RLY1.4 2100,8040 2180,7960 2300,7960 ; 2280,7960 2300,7960 ; Q11.1 2300,7960
NetQ11_2: Q11.2 R115.1 | length 405.6
  Bottom Layer w20: Q11.2 2470,7890 2650,7890 R115.1
NetQ12_1: Q12.1 R116.2 U7.15 | length 5420
  Top Layer w14: v1(4200,7740) 4330,7610 4330,6723.94 4600,6453.94 4600,6150.61 4543,6093.61 4543,5123.92 4600,5066.92 4600,4960 4530,4890 4530,4480 4590,4420 4740,4420 4780,4380 4780,4200 4750,4170 U7.15
  Bottom Layer w14: Q12.1 3320,8180 3400,8100 R116.2 3510,8130 3940,8130 4070,8000 4070,7800 4130,7740 v1(4200,7740)
NetQ12_2: Q12.2 RLY1.1 RLY1.6 | length 1089.9
  Bottom Layer w80: RLY1.6 2690.55,8530.55 2780,8620 2940,8620 2990,8570 2990,8307.6 RLY1.1 3270.91,8400 Q12.2
NetQ13_1: Q13.1 RLY10.5 | length 403.8
  Bottom Layer w40: RLY10.5 6120,7690 6290,7520 Q13.1
NetQ13_2: Q13.2 R139.2 | length 200
  Bottom Layer w40: R139.2 Q13.2
NetQ19_3: Q19.3 R18.2 U10.29 | length 2560.7
  Top Layer w20: v1(6750,5900) 6750,5700 6960,5490 7070,5490 7090,5470 U10.29 ; v1(6750,6230) 6750,6580 6850,6680 R18.2 ; v1(7110,7130) 7150,7130 7160,7120 Q19.3
  Bottom Layer w20: v1(6750,5900) v1(6750,6230) ; R18.2 6900,6680 6870,6710 6870,7080 6920,7130 v1(7110,7130)
NetQ20_1: Q20.1 RLY11.5 | length 514.5
  Bottom Layer w20: Q20.1 7490,7590 7573.35,7673.35 RLY11.5
NetQ20_2: Q20.2 R20.1 | length 260
  Bottom Layer w20: R20.1 7160,7540 Q20.2
NetR1_1: R1.1 U1.2 | length 150.7
  Bottom Layer w14: R1.1@5520,3920 5540,3920 5590,3870 U1.2
NetR2_2: R2.2 U1.4 U10.9 | length 2379.7
  Top Layer w14: v1(5990,4050) 5880,4050 5850,4080 5850,4600 5890,4640 6216.92,4640 6233.45,4623.47 6346.55,4623.47 6363.08,4640 6770,4640 v1(6790,4620)
  Bottom Layer w14: U1.4 5990,4010 v1(5990,4050)
  Bottom Layer w20: R2.2@5520,3820 5680,3820 5830,3970 U1.4
  Bottom Layer w40: v1(6790,4620) U10.9
NetR20_2: R20.2 U10.28 | length 3107.5
  Top Layer w14: v1(6790,5800) 6790,5710 6980,5520 7150,5520 7190,5480 U10.28
  Bottom Layer w20: R20.2 6760,6920 6730,6890 6582.43,6890 6462.43,6770 6270,6770 6240,6740 6240,6592.66 6342.66,6490 6402.43,6490 6510,6382.43 6510,6267.28 6620,6157.28 6620,5926.57 6560,5866.57 6560,5833.43 6583.43,5810 6780,5810 v1(6790,5800)
NetR21_2: R21.2 R22.1 U20.1 | length 381.4
  Bottom Layer w80: R21.2 R22.1 8240,7180 U20.1
NetR27_2: R27.2 U10.7 | length 2906.2
  Top Layer w20: U10.7 6980,5150 7036.57,5150 7046.57,5160 v1(7700,5160)
  Bottom Layer w20: v1(7700,5160) 7740,5200 7740,5570 8120,5950 8120,6560 R27.2
NetR103_2: R103.2 R107.2 R111.2 R115.2 U10.37 | length 7701
  Top Layer w14: R107.2 3220,5620 ; R103.2 3220,4440 3220,7470 3240,7490 3240,7980 3220,8000 R115.2 ; R111.2 3220,6820
  Top Layer w40: v1(4320,4930) 4470,4930 v1(4520,4980)
  Bottom Layer w40: R107.2 3120,5450 3160,5410 3480,5410 3610,5280 3820,5280 4060,5040 4210,5040 v1(4320,4930) ; v1(4520,4980) 4555,5015 5734.29,5015 5779.29,4970 5957.37,4970 6290,5302.63 U10.37
NetR121_2: R121.2 U7.2 | length 223.8
  Bottom Layer w20: U7.2 5010,4170 R121.2
NetR122_2: R122.2 U7.4 | length 215.6
  Bottom Layer w20: U7.4 5030,4370 R122.2
NetR123_2: R123.2 U7.6 | length 207.3
  Bottom Layer w20: U7.6 5050,4570 R123.2
NetR124_2: R124.2 U7.8 | length 199
  Bottom Layer w20: U7.8 5070,4770 R124.2
NetR128_2: R128.2 R129.1 U21.1 | length 516.6
  Bottom Layer w80: R129.1 R128.2 4080,8460 U21.1
NetR130_2: R130.2 TRM1.3 | length 3963.7
  Top Layer w40: v1(4670,6550) 4680,6540 R130.2
  Bottom Layer w40: TRM1.3 1740,7710 1920,7530 3826.86,7530 3926.86,7430 4420,7430 4670,7180 v1(4670,6550)
NetR131_2: R131.2 TRM2.3 | length 3124.2
  Bottom Layer w40: TRM2.3 3573.33,6536.67 3620,6490 4720,6490 4780,6430 R131.2
NetR132_2: R132.2 TRM3.3 | length 4506.2
  Top Layer w40: v1(4170,4970) 4170,5940 v1(4190,5960)
  Bottom Layer w40: TRM3.3 3456.67,5343.33 3570,5230 3799.29,5230 4059.29,4970 v1(4170,4970) ; v1(4190,5960) 4460,6230 4800,6230 4900,6330 R132.2
NetR133_2: R133.2 TRM4.3 | length 5278.9
  Top Layer w40: v1(4220,4330) v1(4220,5890)
  Bottom Layer w40: TRM4.3 1981.01,4150 2091.01,4040 3279.29,4040 3289.29,4050 3839.29,4050 3899.29,4110 3979.29,4110 4009.29,4140 4020,4140 4160,4280 ; 4170,4280 v1(4220,4330) ; v1(4220,5890) 4220,5910 4480,6170 4910,6170 5020,6280 R133.2
NetR134_2: R134.2 U8.1 U12.16 | length 912.1
  Bottom Layer w20: U12.16 5110,5840 U8.1 5220,5870 5220,6380 5260,6420 R134.2
NetR135_2: R135.2 U8.3 U12.14 | length 988.7
  Bottom Layer w20: U12.14 5110,5640 U8.3 5260,5710 5260,6280 5300,6320 R135.2
NetR136_2: R136.2 U8.5 U12.12 | length 1059.4
  Bottom Layer w20: U12.12 5110,5440 U8.5 5160,5400 5300,5540 5300,6160 R136.2
NetR137_2: R137.2 U8.9 U12.10 | length 1415.9
  Bottom Layer w20: U12.10 5080,5240 5090,5230 5090,5170 5109.53,5150.47 5230.47,5150.47 5340,5260 5340,6100 R137.2 ; 5340,5300 U8.9
NetR139_1: R139.1 U10.27 | length 2572.3
  Bottom Layer w20: R139.1 6320,6800 6257.28,6800 6200,6742.72 6200,6520 6260,6460 6390,6460 6480,6370 6480,6254.85 6590,6144.85 6590,5938.99 6530,5878.99 6530,5821.01 6590,5761.01 6590,5720 6710,5600 7220,5600 7290,5530 U10.27
NetRLY1_2: RLY1.2 TRM1.1 | length 1220.6
  Bottom Layer w80: TRM1.1 1820,8230 1900,8310 2790.75,8310 RLY1.2
NetRLY1_7: RLY1.7 TRM1.0 | length 1216.4
  Bottom Layer w80: TRM1.0 1830,8480 1900,8410 2790.75,8410 RLY1.7
NetRLY2_2: RLY2.2 TRM2.1 | length 1226.1
  Bottom Layer w80: TRM2.1 1826.67,7036.67 1920,7130 2790.75,7130 RLY2.2
NetRLY2_7: RLY2.7 TRM2.0 | length 1216.4
  Bottom Layer w80: TRM2.0@1740,7300 1850,7300 1920,7230 2790.75,7230 RLY2.7
NetRLY3_2: RLY3.2 TRM3.1 | length 1223.3
  Bottom Layer w80: TRM3.1 1873.33,5843.33 1960,5930 2790.75,5930 RLY3.2
NetRLY3_7: RLY3.7 TRM3.0 | length 1213.7
  Bottom Layer w80: TRM3.0 1886.67,6093.33 1950,6030 2790.75,6030 RLY3.7
NetRLY4_2: RLY4.2 TRM4.1 | length 1212.3
  Bottom Layer w80: TRM4.1 1900,4650 1970,4720 2800.75,4720 RLY4.2
NetRLY4_7: RLY4.7 TRM4.0 | length 1224.7
  Bottom Layer w80: TRM4.0 1910,4900 1990,4820 2780.75,4820 RLY4.7
NetU3_1: U3.1 U10.24 | length 1241.1
  Top Layer w20: U3.1 6860,5690 7000,5550 7510,5550 7590,5470 U10.24
NetU3_2: U3.2 U10.18 | length 1937.8
  Top Layer w20: U3.2 6950,6050 6960,6040 6960,5960 6890,5890 6890,5740 v1(6950,5680)
  Bottom Layer w20: v1(6950,5680) 6960,5670 7290,5670 7440,5520 7440,5010 U10.18
NetU3_4: U3.4 U10.17 | length 2008.8
  Top Layer w20: U3.4 6950,6150 6990,6110 6990,5940 6950,5900 v1(6950,5750)
  Bottom Layer w20: v1(6950,5750) 6900,5700 6900,5660 6930,5630 7260,5630 7340,5550 7340,5060 7580,4820 U10.17@7580,4760
NetU3_8: U3.8 U10.23 | length 1507.8
  Top Layer w14: U3.8 6585,5865 v1(6600,5850)
  Bottom Layer w14: v1(6600,5850) 6930,5850 7080,5700 7450,5700 7690,5460 U10.23
NetU4_7: U4.7 U10.2 | length 4290.3
  Top Layer w20: v1(5740,5240) v1(5860,5240) ; v1(5860,5020) 5860,4900 5900,4860 6090,4860 U10.2 ; v1(5880,5890) 5880,6130 6060,6310 6130,6310 v1(6170,6350) ; U4.7 6965,7785 v1(6990,7760)
  Bottom Layer w20: v1(5740,5240) 5740,5770 5860,5890 v1(5880,5890) ; v1(5860,5020) v1(5860,5240) ; v1(6170,6350) 6170,6755.15 6244.85,6830 6274.85,6830 6444.85,7000 6650,7000 6690,7040 6690,7380 6760,7450 6990,7450 7020,7480 7020,7730 v1(6990,7760)
NetU5_1: U5.1 U10.26 | length 1602
  Top Layer w20: v1(6590,4940) 6610,4960 6650,4960 6950,5260 7370,5260 7390,5280 U10.26
  Bottom Layer w20: U5.1 6320.47,4640.47 6440.47,4640.47 6440.47,4780.51 6590,4930.04 v1(6590,4940)
NetU6_3: U6.3 U10.10 | length 633.8
  Bottom Layer w20: U6.3 6580,4500 6830,4500 6890,4560 U10.10
NetU6_4: U6.4 U10.25 | length 1514.2
  Top Layer w20: v1(6620,4890) 6622.43,4890 6772.43,5040 6780,5040 ; 6770,5030 6780,5040 ; U10.25 7490,5320 7400,5230 6970,5230 6780,5040
  Bottom Layer w20: U6.4 6420,4570 6540.47,4690.47 6540.47,4809.53 6570,4839.06 ; 6570,4840 v1(6620,4890)
NetU7_1: U7.1 U10.33 | length 2565.2
  Bottom Layer w14: U7.1 5010,4070 5360,4420 5360,4860 5400,4900 5686.65,4900 5736.65,4850 6000,4850 6390,5240 6590,5240 6690,5340 U10.33
NetU7_3: U7.3 U10.34 | length 2309
  Bottom Layer w20: U7.3 5010,4270 5150,4410 5200,4410 5330,4540 5330,4880 5377,4927 5697.84,4927 5742.84,4882 5993.82,4882 6378,5266.18 6378,5268 6380,5270 6500,5270 U10.34
NetU7_5: U7.5 U10.35 | length 2062.8
  Bottom Layer w14: 5010,4470 5110,4570 5200,4570 5300,4670 5300,4900 5354,4954 5709.02,4954 5754.02,4909 5982.63,4909 6351,5277.37 6351,5281 6370,5300 6430,5300 U10.35
  Bottom Layer w20: U7.5 5010,4470
NetU7_7: U7.7 U10.36 | length 1807.3
  Bottom Layer w14: U7.7 5040,4670 5120,4750 5200,4750 5276,4826 5276,4909.94 5280,4913.94 5280,4930 5328,4978 5718.96,4978 5763.96,4933 5972.69,4933 6327,5287.31 6327,5297 U10.36
NetU8_2: U8.2 U10.3 | length 2133.6
  Top Layer w20: U8.2 5290,5700 5360,5630 5360,5190 5420,5130 6130,5130 6290,4970 6290,4890 6340,4840 6340,4739.96 6310.51,4710.47 6269.49,4710.47 6252.96,4727 6223,4727 U10.3
NetU8_4: U8.4 U10.4 | length 1695.6
  Top Layer w20: U8.4 5280,5500 5330,5450 5330,5177.28 5407.28,5100 6102.43,5100 6220,4982.43 6220,4980 6240,4960 6240,4810 U10.4
NetU8_6: U8.6 U10.5 | length 1820
  Top Layer w20: U8.6 5250,5300 5290,5260 5290,5174.85 5394.85,5070 6090,5070 6190,4970 6190,4900 6140,4850 6140,4739.96 6182.96,4697 6240.53,4697 6257.06,4680.47 6322.94,4680.47 6339.47,4697 6387,4697 6390,4700 U10.5
NetU8_8: U8.8 U10.6 | length 1320.4
  Top Layer w20: U8.8 5490,5160 6257.57,5160 6490,4927.57 U10.6
V5: C28.1 ICSP.2 P_DISP.2 Q19.1 R2.1 R4.2 R9.3 R134.1 R135.1 R136.1 R137.1 RLY1.5 RLY2.5 RLY3.5 RLY4.5 RLY10.2 RLY11.2 U4.8 U5.8 U6.2 U6.8 U8.14 | length 24633.3
  Top Layer w20: v1(6993.31,6976.69) Q19.1 ; U4.8 7054.49,7845.51 7054.49,7755.51 v1(7060,7750)
  Top Layer w40: 1993.35,7326.65 RLY2.5 ; 1996.65,6126.65 RLY3.5 ; RLY4.5 1990,5036.65 1990,8460 2036.65,8506.65 RLY1.5 ; U6.2 6610,4390 6710,4290 U6.8
  Top Layer w80: v1(1990,4480) 1990,4816.65 RLY4.5 ; v1(3310,4220) 3470,4060 3872.72,4060 4032.72,4220 4320,4220 4540,4000 4540,3860 4560,3840 4830,3840 ; v1(4690,4920) 4690,5057.53 4602.44,5145.09 4602.44,6067.56 4674.88,6140 5110,6140 v1(5450,5800) 5570,5800 5720,5650 5940,5650 5980,5690 ICSP.2 ; v1(4830,3950) 4840,3950 4830,3940 4830,3840 ; R2.1 4830,3840 ; v1(6620,7270) 6650,7270 6660,7280 ; v1(6660,7570) 6660,7280 ; v1(6993.31,6976.69) 6980,6990 6980,7170 7030,7220 ; C28.1 7030,7220 ; R4.2 7510,6270 7560,6220 7560,5690 7730,5520 v1(8110,5520) ; v1(8100,4720) 8151,4669 R9.3 ; 6660,7280 6720,7220 7030,7220
  Bottom Layer w20: v1(7050,7250) 7050,7440 7060,7450 v1(7060,7750)
  Bottom Layer w40: R2.1 5221.01,3840 5226,3844.99 5290,3908.99 5290,4098.99 5391.01,4200 6240,4200 6250,4210 U5.8 6250,4360 6260,4370 6660,4370 6710,4320 U6.8
  Bottom Layer w80: v1(1990,4480) 1990,4460 2230,4220 v1(3310,4220) ; v1(4690,4920) 4750,4920 4860,4810 4860,3980 v1(4830,3950) ; v1(5450,5800) 5450,5810 R137.1 R136.1 R135.1 R134.1 5760,6730 5920,6890 6250,6890 6420,7060 6540,7060 6620,7140 v1(6620,7270) ; 5880,5450 5880,5610 5980,5710 ICSP.2 ; RLY10.2 6183.35,8046.65 6260,7970 6260,7690 6330,7620 6660,7620 v1(6660,7570) ; v1(6993.31,6976.69) 7350,6620 7350,6470 7380,6440 R4.2 ; C28.1 7490,7287.17 7490,7443.35 RLY11.2 ; 8040,4650 8110,4720 8110,5070 ; v1(8110,5520) 8110,5070 ; P_DISP.2 8120,5080 8110,5070
V12: C128.1 R128.1 TRM1.2 TRM2.2 TRM3.2 TRM4.2 U7.10 U7.12 U7.14 U7.16 U21.3 | length 12745.3
  Top Layer w20: U7.14 4600,4270 4580,4250 4580,4180 4580,4100 4610,4070 U7.16 4770,4070 4820,4120 4820,4410 4760,4470 U7.12 4620,4470 4590,4500 4590,4640 4620,4670 U7.10
  Top Layer w80: C128.1 4300,8057.17 4300,8380 4340,8420 R128.1 ; v1(4430,4370) 4430,4290 4540,4180 4580,4180
  Bottom Layer w80: 1593.33,5593.33 TRM3.2 ; 1593.33,6786.67 TRM2.2 ; U21.3 4280,8580 R128.1 ; C128.1 4397.17,7767.17 4250,7620 2100,7620 TRM1.2 1640,7980 1590,7930 1590,4550 TRM4.2 1830,4400 2120,4110 3250.29,4110 3260.29,4120 3810.29,4120 4110.29,4420 4380,4420 v1(4430,4370)
V33: C24.2 U3.3 U3.5 U3.6 U18.1 | length 1172.9
  Top Layer w20: U18.1 6040,6030 6010,6060 6010,6160 6070,6220 6350,6220 6400,6170 C24.2 ; C24.2@6410,6150 U3.5 U3.6 U3.3
V36: B1.1 C10.1 C11.1 F1.3 F1.4 F2.3 F2.4 F3.3 F3.4 F4.3 F4.4 U21.2 | length 8648.9
  Top Layer w100: F4.3 3707.24,4440 3970,4440 3970,7610 3767.4,7812.6 F1.4 ; F3.4 3892.6,5432.6 ; F2.4 3967.4,6632.6 ; F1.3 3989.13,8029.13 4040,8080 4120,8080 4180,8140 v1(4180,8580)
  Bottom Layer w100: F4.4 F4.3 ; F3.4 F3.3 ; F2.4 F2.3 ; F1.4 F1.3 ; v1(3970,7520) 3965,7515 B1.1 4790,7310 4965.28,7134.72 C11.1@5270,7134.72 ; v1(4180,8580) U21.2 ; C11.1 C10.1
V_IN: C22.1 D24.2 J1.2 J1.2A J1.2B U20.2 | length 1563.7
  Bottom Layer w80: 7932.83,7382.83 7860,7310 D24.2 7860,7070 7880,7050 8230,7050 8300,6980 U20.2 ; 7940,7390 8020,7390 8110,7300 8380,7300 8444.72,7364.72 J1.2A
VCC: C21.1 C23.2 D10.2 D11.1 P3.2 Q19.2 R3.2 R18.1 R21.1 U10.11 U10.32 U18.3 U20.3 | length 8269.8
  Top Layer w20: R3.2 5800,4590 5877,4667 6228.1,4667 6244.63,4650.47 6335.37,4650.47 6351.9,4667 6781.18,4667 6788.18,4660 6930,4660 6973.19,4703.19 6990,4720 U10.11 ; U18.3 6294.88,6130 C23.2 ; Q19.2 7253.31,6976.69 7270,6960
  Top Layer w80: v1(6260,6320) 6260,6670 6270,6680 P3.2 ; D11.1 7270,6320 7420,6470 7420,6777.17 C21.1 7422.83,6807.17 7270,6960
  Bottom Layer w40: U18.3 6100,6180 6140,6220 6160,6220 v1(6260,6320) ; U10.32 6790,5240 6990,5040 U10.11
  Bottom Layer w80: v1(6260,6320) 6330,6320 6530,6120 6530,5963.85 6470,5903.85 6470,5796.15 6530,5736.15 6530,5650 6670,5510 6720,5510 6790,5440 U10.32 ; P3.2 R18.1 ; D10.2 R18.1 ; D11.1 6850,6320 6780,6390 6780,6600 6700,6680 R18.1 ; v1(7250,6310) 7320,6240 7800,6240 8000,6440 8000,6710 ; R21.1 8000,6710 ; U20.3 8340,6770 8250,6680 8030,6680 8000,6710
pads on no net: P2.0 P4.0 RLY10.4 RLY11.3 U5.4 U6.1 U8.10 U8.11 U8.12 U8.13

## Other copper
Top Layer:
  rectangle net GND: 7570,3770 7960,4240

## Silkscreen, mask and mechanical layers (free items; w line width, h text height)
Mechanical 1:
  lines w10: 1310,3700 1310,8970 1350,8970 8550,8970 8550,3700 1310,3700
